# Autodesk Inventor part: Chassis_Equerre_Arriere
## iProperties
Created: 2008-12
Part Number: Chassis_Equerre_Arriere
Document SubType Name: Sheet Metal
Designer: claivier
Author: claivier
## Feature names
1. Perçage1 [Hole]
2. Perçage2 [Hole]
3. Chanfrein1 [Chamfer]
4. Plaque1
5. Pli1
